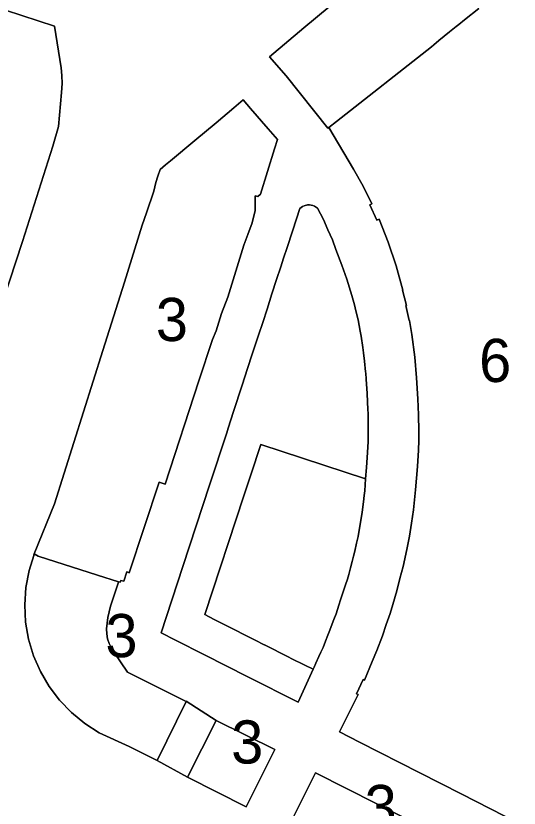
# Model space of a CAD drawing. Extents: x 598968 to 613553, y 4409678 to 4430833.
# Drawn here: x 608782.2 to 608922.1, y 4415660.4 to 4415880.5 of the extents above; entities that cross this region are included whole.
import ezdxf

# ---------------------------------------------------------------- set-up
doc = ezdxf.new("R2010")
doc.units = 0
for name, color, linetype in [('1', 7, 'Continuous'), ("ZONA 3. ILLES  D'EDIFICIS ENTRE MITGERES. EIXAMPLE.", 7, 'Continuous'), ('ZONA 6. EDIFICIS DE PISOS_ AÏLLATS I EN PARCEL.LES', 7, 'Continuous')]:
    doc.layers.add(name, color=color, linetype=linetype)

msp = doc.modelspace()

# ---------------------------------------------------------------- linework, layer by layer
at = {"layer": '1'}
for points in [[(608922.0848, 4415656.0922), (608905.99, 4415664.3368), (608894.5151, 4415670.2115), (608877.7153, 4415678.7311), (608872.1353, 4415681.591), (608877.3753, 4415691.9507), (608876.9253, 4415692.1009), (608878.7052, 4415696.1109), (608879.1052, 4415695.9309), (608881.2852, 4415701.1359), (608882.5452, 4415704.1709), (608884.1051, 4415708.2709), (608885.1701, 4415711.3809), (608886.2351, 4415714.4908), (608886.9751, 4415716.9608), (608888.125, 4415720.7908), (608888.975, 4415724.1608), (608889.825, 4415727.5307), (608890.885, 4415732.2807), (608891.575, 4415735.9307), (608892.1749, 4415739.6106), (608892.6949, 4415743.3005), (608893.3099, 4415748.8505), (608893.7999, 4415755.2954), (608894.1149, 4415759.8903), (608894.1798, 4415762.5103), (608894.2448, 4415765.1303), (608894.0898, 4415769.6302), (608893.9348, 4415774.1302), (608893.5148, 4415779.9251), (608893.0948, 4415785.72), (608892.2748, 4415791.9799), (608891.6248, 4415795.8898), (608891.4851, 4415795.8585), (608890.5548, 4415800.0098), (608890.7512, 4415800.0631), (608889.6329, 4415804.3124), (608889.7748, 4415804.3497), (608887.9355, 4415811.0367), (608885.7333, 4415817.6132), (608883.1748, 4415824.0593), (608882.5148, 4415823.7693), (608880.6374, 4415828.0603), (608881.1074, 4415828.2848), (608878.7649, 4415833.1899), (608876.0498, 4415837.899), (608869.1849, 4415849.4888), (608869.1711, 4415849.5075), (608868.9091, 4415849.305), (608857.3172, 4415863.8302), (608852.705, 4415869.1482), (608862.2966, 4415877.1663), (608880.7115, 4415892.5602)], [(608880.7115, 4415892.5602), (608862.2966, 4415877.1663), (608852.705, 4415869.1482), (608857.3172, 4415863.8302), (608868.9091, 4415849.305), (608869.1711, 4415849.5075), (608871.3507, 4415851.1924), (608897.7532, 4415871.9606), (608898.4164, 4415872.5136), (608899.7827, 4415873.6528), (608902.7647, 4415876.1135), (608904.5467, 4415877.5412), (608905.354, 4415878.1767), (608906.9198, 4415879.4233), (608910.9111, 4415882.606)], [(608770.206, 4415885.1265), (608792.9757, 4415877.627), (608794.8358, 4415866.0772), (608794.9658, 4415863.9272), (608795.0958, 4415861.7773), (608794.8758, 4415859.2273), (608794.1058, 4415849.7874), (608792.4708, 4415844.3325), (608784.0394, 4415817.8481), (608776.7962, 4415795.7978)]]:
    msp.add_lwpolyline(points, dxfattribs=at)
for points in [[(608812.4654, 4415806.5784), (608817.3756, 4415822.3482), (608818.5327, 4415825.7991), (608820.5456, 4415831.7981), (608821.1547, 4415834.1919), (608821.7102, 4415835.9529), (608822.2955, 4415837.8081), (608823.8361, 4415839.1014), (608824.7465, 4415839.8656), (608825.2123, 4415840.2567), (608831.953, 4415845.9157), (608837.9052, 4415850.8382), (608842.7752, 4415854.9682), (608845.3801, 4415857.1987), (608847.4307, 4415854.8189), (608852.3263, 4415849.1431), (608854.893, 4415846.1663), (608854.1451, 4415843.6186), (608850.2392, 4415830.9477), (608849.4641, 4415830.3639), (608848.7011, 4415830.5188), (608848.7039, 4415826.4498), (608847.8891, 4415822.9861), (608846.6809, 4415819.804), (608845.6053, 4415816.8088), (608841.1754, 4415802.3989), (608839.3754, 4415797.8089), (608837.8504, 4415793.0189), (608836.8854, 4415790.6189), (608833.0655, 4415779.119), (608823.7367, 4415750.4019), (608822.0858, 4415750.9192), (608813.766, 4415725.7994), (608813.3288, 4415725.9349), (608813.056, 4415726.0291), (608812.216, 4415723.4394), (608811.3936, 4415723.6594), (608811.266, 4415723.1394), (608810.7948, 4415723.2858), (608810.7444, 4415723.1336), (608808.556, 4415716.4594), (608807.7803, 4415713.3736), (608807.4461, 4415710.2095), (608807.4963, 4415708.8058), (608807.7432, 4415707.4231), (608808.1819, 4415706.0887), (608808.8036, 4415704.8293), (608809.5961, 4415703.6696), (608813.296, 4415698.1897), (608829.5558, 4415690.0201), (608829.588, 4415690.0856), (608837.9157, 4415684.7703), (608854.162, 4415676.7139), (608846.2557, 4415660.7708), (608829.9683, 4415668.9556), (608821.4948, 4415673.6487), (608821.466, 4415673.5902), (608813.7061, 4415677.47), (608805.3962, 4415681.3198), (608801.3679, 4415683.9017), (608797.6709, 4415686.9391), (608794.3563, 4415690.3898), (608791.4701, 4415694.206), (608789.0523, 4415698.3349), (608787.1363, 4415702.7192), (608785.7608, 4415707.3407), (608784.9421, 4415712.0925), (608784.6918, 4415716.9079), (608785.0134, 4415721.719), (608785.9024, 4415726.4582), (608787.2064, 4415730.6129), (608787.2779, 4415730.8406), (608787.3463, 4415731.0588), (608787.363, 4415731.049), (608793.0161, 4415744.8987), (608806.4059, 4415787.5784)], [(608840.8271, 4415764.7093), (608841.2426, 4415765.9879), (608842.7283, 4415770.5526), (608845.1213, 4415777.9042), (608846.6397, 4415782.5694), (608847.9253, 4415786.5192), (608849.6878, 4415791.8175), (608850.8653, 4415795.3573), (608852.0446, 4415799.0167), (608853.406, 4415803.2726), (608854.7061, 4415807.2897), (608855.855, 4415810.8024), (608856.6472, 4415813.2251), (608857.6205, 4415816.2008), (608859.1048, 4415820.7458), (608860.2137, 4415824.1501), (608861.135, 4415826.9789), (608861.915, 4415827.5689), (608862.365, 4415827.7789), (608863.315, 4415828.0089), (608863.56, 4415828.0139), (608863.805, 4415828.0189), (608864.775, 4415827.849), (608865.235, 4415827.669), (608866.055, 4415827.129), (608867.715, 4415823.9191), (608868.955, 4415821.1041), (608870.195, 4415818.2892), (608871.1736, 4415815.6391), (608872.7812, 4415811.2861), (608874.2349, 4415807.3494), (608875.5749, 4415802.8095), (608876.3049, 4415800.1995), (608876.7349, 4415798.5295), (608877.3797, 4415796.0976), (608877.9527, 4415792.916), (608878.1669, 4415791.5695), (608878.6417, 4415788.3662), (608878.865, 4415786.8597), (608879.1115, 4415784.5844), (608879.4291, 4415781.6538), (608879.475, 4415781.2298), (608879.5846, 4415779.5971), (608879.855, 4415775.5699), (608880.0783, 4415771.0537), (608880.125, 4415770.11), (608880.1435, 4415768.7625), (608880.1604, 4415767.5331), (608880.1675, 4415766.0152), (608880.0885, 4415762.2281), (608879.955, 4415759.1901), (608879.6507, 4415755.0622), (608879.4304, 4415751.9321), (608879.1951, 4415748.5902), (608879.042, 4415747.2914), (608878.8312, 4415745.5025), (608878.4951, 4415742.6503), (608877.3151, 4415735.8604), (608876.8846, 4415733.9723), (608876.3842, 4415731.7776), (608876.0763, 4415730.4266), (608875.6908, 4415728.96), (608875.2102, 4415727.1555), (608874.7158, 4415725.2991), (608874.3752, 4415724.0205), (608873.8655, 4415722.4677), (608873.2232, 4415720.5112), (608872.4867, 4415718.2675), (608872.0073, 4415716.8071), (608871.2069, 4415714.3687), (608870.6219, 4415712.8204), (608870.134, 4415711.5564), (608869.4782, 4415709.8572), (608868.9153, 4415708.4006), (608868.2754, 4415706.741), (608867.6153, 4415705.0306), (608867.0013, 4415703.6924), (608866.4526, 4415702.4962), (608865.6141, 4415700.6685), (608865.1133, 4415699.5771), (608864.828, 4415698.9553), (608860.6555, 4415689.8607), (608846.7356, 4415696.8503), (608834.6657, 4415702.985), (608826.6074, 4415707.0808), (608822.5959, 4415709.1198), (608828.6357, 4415727.5096), (608836.0406, 4415750.1094)], [(608879.4304, 4415751.9321), (608879.6507, 4415755.0622), (608879.955, 4415759.1901), (608880.0885, 4415762.2281), (608880.1675, 4415766.0152), (608880.1604, 4415767.5331), (608880.1435, 4415768.7625), (608880.125, 4415770.11), (608880.0783, 4415771.0537), (608879.855, 4415775.5699), (608879.5846, 4415779.5971), (608879.475, 4415781.2298), (608879.4291, 4415781.6538), (608879.1115, 4415784.5844), (608878.865, 4415786.8597), (608878.6417, 4415788.3662), (608878.1669, 4415791.5695), (608877.9527, 4415792.916), (608877.3797, 4415796.0976), (608876.7349, 4415798.5295), (608876.3049, 4415800.1995), (608875.5749, 4415802.8095), (608874.2349, 4415807.3494), (608872.7812, 4415811.2861), (608871.1736, 4415815.6391), (608870.195, 4415818.2892), (608868.955, 4415821.1041), (608867.715, 4415823.9191), (608866.055, 4415827.129), (608865.235, 4415827.669), (608864.775, 4415827.849), (608863.805, 4415828.0189), (608863.56, 4415828.0139), (608863.315, 4415828.0089), (608862.365, 4415827.7789), (608861.915, 4415827.5689), (608861.135, 4415826.9789), (608860.2137, 4415824.1501), (608859.1048, 4415820.7458), (608857.6205, 4415816.2008), (608856.6472, 4415813.2251), (608855.855, 4415810.8024), (608854.7061, 4415807.2897), (608853.406, 4415803.2726), (608852.0446, 4415799.0167), (608850.8653, 4415795.3573), (608849.6878, 4415791.8175), (608847.9253, 4415786.5192), (608846.6397, 4415782.5694), (608845.1213, 4415777.9042), (608842.7283, 4415770.5526), (608841.2426, 4415765.9879), (608840.8271, 4415764.7093), (608836.0406, 4415750.1094), (608828.6357, 4415727.5096), (608822.5959, 4415709.1198), (608826.6074, 4415707.0808), (608834.6657, 4415702.985), (608846.7356, 4415696.8503), (608860.6555, 4415689.8607), (608864.828, 4415698.9553), (608862.5328, 4415700.1079), (608858.7675, 4415701.9985), (608858.0659, 4415702.3509), (608851.2813, 4415705.7629), (608851.2671, 4415705.77), (608848.7204, 4415707.059), (608846.1367, 4415708.3723), (608842.7097, 4415710.114), (608837.3604, 4415712.8329), (608834.7727, 4415714.1481), (608845.6051, 4415747.1867), (608847.5223, 4415753.035), (608850.2681, 4415761.4102)], [(608879.4304, 4415751.9321), (608850.2681, 4415761.4102), (608847.5223, 4415753.035), (608845.6051, 4415747.1867), (608834.7727, 4415714.1481), (608837.3604, 4415712.8329), (608842.7097, 4415710.114), (608846.1367, 4415708.3723), (608848.7204, 4415707.059), (608851.2671, 4415705.77), (608851.2813, 4415705.7629), (608858.0659, 4415702.3509), (608858.7675, 4415701.9985), (608862.5328, 4415700.1079), (608864.828, 4415698.9553), (608865.1133, 4415699.5771), (608865.6141, 4415700.6685), (608866.4526, 4415702.4962), (608867.0013, 4415703.6924), (608867.6153, 4415705.0306), (608868.2754, 4415706.741), (608868.9153, 4415708.4006), (608869.4782, 4415709.8572), (608870.134, 4415711.5564), (608870.6219, 4415712.8204), (608871.2069, 4415714.3687), (608872.0073, 4415716.8071), (608872.4867, 4415718.2675), (608873.2232, 4415720.5112), (608873.8655, 4415722.4677), (608874.3752, 4415724.0205), (608874.7158, 4415725.2991), (608875.2102, 4415727.1555), (608875.6908, 4415728.96), (608876.0763, 4415730.4266), (608876.3842, 4415731.7776), (608876.8846, 4415733.9723), (608877.3151, 4415735.8604), (608878.4951, 4415742.6503), (608878.8312, 4415745.5025), (608879.042, 4415747.2914), (608879.1951, 4415748.5902)], [(608837.9157, 4415684.7703), (608829.588, 4415690.0856), (608829.5558, 4415690.0201), (608821.4948, 4415673.6487), (608829.9683, 4415668.9556)], [(608865.4655, 4415670.151), (608899.5386, 4415652.9888), (608892.7452, 4415639.5019), (608858.7456, 4415656.6811)]]:
    msp.add_lwpolyline(points, close=True, dxfattribs=at)
at = {"layer": "ZONA 3. ILLES  D'EDIFICIS ENTRE MITGERES. EIXAMPLE."}
msp.add_lwpolyline([(608776.7962, 4415795.7978), (608784.0394, 4415817.8481), (608792.4708, 4415844.3325), (608794.1058, 4415849.7874), (608794.8758, 4415859.2273), (608795.0958, 4415861.7773), (608794.9658, 4415863.9272), (608794.8358, 4415866.0772), (608792.9757, 4415877.627), (608770.206, 4415885.1265)], dxfattribs=at)
for points in [[(608810.7948, 4415723.2858), (608811.266, 4415723.1394), (608811.3936, 4415723.6594), (608812.216, 4415723.4394), (608813.056, 4415726.0291), (608813.3288, 4415725.9349), (608813.766, 4415725.7994), (608822.0858, 4415750.9192), (608823.7367, 4415750.4019), (608833.0655, 4415779.119), (608836.8854, 4415790.6189), (608837.8504, 4415793.0189), (608839.3754, 4415797.8089), (608841.1754, 4415802.3989), (608845.6053, 4415816.8088), (608846.6809, 4415819.804), (608847.8891, 4415822.9861), (608848.7039, 4415826.4498), (608848.7011, 4415830.5188), (608849.4641, 4415830.3639), (608850.2392, 4415830.9477), (608854.1451, 4415843.6186), (608854.893, 4415846.1663), (608852.3263, 4415849.1431), (608847.4307, 4415854.8189), (608845.3801, 4415857.1987), (608842.7752, 4415854.9682), (608837.9052, 4415850.8382), (608831.953, 4415845.9157), (608825.2123, 4415840.2567), (608824.7465, 4415839.8656), (608823.8361, 4415839.1014), (608822.2955, 4415837.8081), (608821.7102, 4415835.9529), (608821.1547, 4415834.1919), (608820.5456, 4415831.7981), (608818.5327, 4415825.7991), (608817.3756, 4415822.3482), (608812.4654, 4415806.5784), (608806.4059, 4415787.5784), (608793.0161, 4415744.8987), (608787.363, 4415731.049), (608788.4562, 4415730.4089), (608804.9461, 4415725.1092), (608810.796, 4415723.2894)], [(608787.363, 4415731.049), (608787.3463, 4415731.0588), (608787.2779, 4415730.8406), (608787.2064, 4415730.6129), (608785.9024, 4415726.4582), (608785.0134, 4415721.719), (608784.6918, 4415716.9079), (608784.9421, 4415712.0925), (608785.7608, 4415707.3407), (608787.1363, 4415702.7192), (608789.0523, 4415698.3349), (608791.4701, 4415694.206), (608794.3563, 4415690.3898), (608797.6709, 4415686.9391), (608801.3679, 4415683.9017), (608805.3962, 4415681.3198), (608813.7061, 4415677.47), (608821.466, 4415673.5902), (608821.4948, 4415673.6487), (608829.5558, 4415690.0201), (608813.296, 4415698.1897), (608809.5961, 4415703.6696), (608808.8036, 4415704.8293), (608808.1819, 4415706.0887), (608807.7432, 4415707.4231), (608807.4963, 4415708.8058), (608807.4461, 4415710.2095), (608807.7803, 4415713.3736), (608808.556, 4415716.4594), (608810.7444, 4415723.1336), (608810.7948, 4415723.2858), (608810.796, 4415723.2894), (608804.9461, 4415725.1092), (608788.4562, 4415730.4089)], [(608829.9683, 4415668.9556), (608846.2557, 4415660.7708), (608854.162, 4415676.7139), (608837.9157, 4415684.7703)], [(608899.5386, 4415652.9888), (608865.4655, 4415670.151), (608858.7456, 4415656.6811), (608892.7452, 4415639.5019)]]:
    msp.add_lwpolyline(points, close=True, dxfattribs=at)
at = {"layer": 'ZONA 6. EDIFICIS DE PISOS_ AÏLLATS I EN PARCEL.LES'}
msp.add_lwpolyline([(608910.9111, 4415882.606), (608906.9198, 4415879.4233), (608905.354, 4415878.1767), (608904.5467, 4415877.5412), (608902.7647, 4415876.1135), (608899.7827, 4415873.6528), (608898.4164, 4415872.5136), (608897.7532, 4415871.9606), (608871.3507, 4415851.1924), (608869.1711, 4415849.5075), (608869.1849, 4415849.4888), (608876.0498, 4415837.899), (608878.7649, 4415833.1899), (608881.1074, 4415828.2848), (608880.6374, 4415828.0603), (608882.5148, 4415823.7693), (608883.1748, 4415824.0593), (608885.7333, 4415817.6132), (608887.9355, 4415811.0367), (608889.7748, 4415804.3497), (608889.6329, 4415804.3124), (608890.7512, 4415800.0631), (608890.5548, 4415800.0098), (608891.4851, 4415795.8585), (608891.6248, 4415795.8898), (608892.2748, 4415791.9799), (608893.0948, 4415785.72), (608893.5148, 4415779.9251), (608893.9348, 4415774.1302), (608894.0898, 4415769.6302), (608894.2448, 4415765.1303), (608894.1798, 4415762.5103), (608894.1149, 4415759.8903), (608893.7999, 4415755.2954), (608893.3099, 4415748.8505), (608892.6949, 4415743.3005), (608892.1749, 4415739.6106), (608891.575, 4415735.9307), (608890.885, 4415732.2807), (608889.825, 4415727.5307), (608888.975, 4415724.1608), (608888.125, 4415720.7908), (608886.9751, 4415716.9608), (608886.2351, 4415714.4908), (608885.1701, 4415711.3809), (608884.1051, 4415708.2709), (608882.5452, 4415704.1709), (608881.2852, 4415701.1359), (608879.1052, 4415695.9309), (608878.7052, 4415696.1109), (608876.9253, 4415692.1009), (608877.3753, 4415691.9507), (608872.1353, 4415681.591), (608877.7153, 4415678.7311), (608894.5151, 4415670.2115), (608905.99, 4415664.3368), (608922.0848, 4415656.0922)], dxfattribs=at)

# ---------------------------------------------------------------- texts
at = {"layer": "ZONA 3. ILLES  D'EDIFICIS ENTRE MITGERES. EIXAMPLE."}
for p in [(608821.128, 4415790.169), (608807.1238, 4415702.3245), (608842.0651, 4415672.7706), (608879.1421, 4415654.8265)]:
    msp.add_text('3', height=12, dxfattribs=at).set_placement(p)
at = {"layer": 'ZONA 6. EDIFICIS DE PISOS_ AÏLLATS I EN PARCEL.LES'}
msp.add_text('6', height=12, dxfattribs=at).set_placement((608910.9605, 4415778.7919))

doc.saveas('drawing.dxf')
